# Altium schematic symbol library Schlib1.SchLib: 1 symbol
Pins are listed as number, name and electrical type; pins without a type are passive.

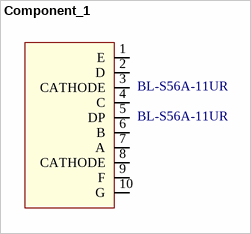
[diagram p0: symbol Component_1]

## Component_1
designator BL-S56A-11UR, comment BL-S56A-11UR
footprint BL-S56A-11UR
pins: 1 E, 2 D, 3 CATHODE, 4 C, 5 DP, 6 B, 7 A, 8 CATHODE, 9 F, 10 G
